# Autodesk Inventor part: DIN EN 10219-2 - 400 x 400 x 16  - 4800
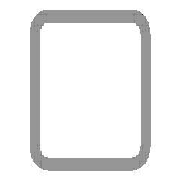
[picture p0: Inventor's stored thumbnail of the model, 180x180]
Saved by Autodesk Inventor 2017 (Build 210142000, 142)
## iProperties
IsCustomPart: 1
Created: 2017-11
Part Number: DIN EN 10219-2 - 400 x 400 x 16  - 4800
Material: Steel, Mild
Description: Cold formed welded structural hollow sections of non-alloy and fine grain structural steel
Document SubType Name: Modeling
Standard: DIN
Designer: iusti
Standard Revision: 2006-07
Standards Organization: DIN
Language: en-US
Size Designation: 400 x 400 x 16
Categories: <MemberInstance><Categories><Category DisplayName="Structural Shapes" InternalName="089c4875-fa83-4c05-b084-43b9cc11f5ed" Mnemonic="GRDR"><CategoryParameter Dis
Stock Number: 400 x 400 x 16
Density: 7.85 g/cm^3
Appearance: Semi-Polished
Mass: 884622 g
Surface Area: 141333 cm^2
Volume: 112691 cm^3
_CCFamilyMember: 142
_CCFamilyDisplayName: DIN EN 10219-2 (Square Hollow Section - Cold Formed) - Cold formed welded structural hollow sections of non-alloy and fine grain structural steel
_FrameMemberDoc: Frame Member File
_Version: 15.0.0
_GetPNFromCC: 1
G_L: 4800.000 mm
G_W: 400.000 mm
G_H: 400.000 mm
+3C696B27-B370-4381-981B-8782BFEB3638+CUTDETAIL1: Cut
Author: iusti
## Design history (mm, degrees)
node "Start plane"
node "End plane"
sketch "Sketch"
  geometry: L1 (-200, -152)-(-200, 152); L2 (-152, 200)-(152, 200); L3 (200, 152)-(200, -152); L4 (152, -200)-(-152, -200); L5 (-152, 184)-(152, 184); L6 (184, 152)-(184, -152); L7 (152, -184)-(-152, -184); L8 (-184, -152)-(-184, 152); L9 (0, 293.918)-(0, -293.918) reference; L10 (-293.918, 0)-(293.918, 0) reference; A1 r 48 centre (-152, -152) between (-200, -152) and (-152, -200); A2 r 48 centre (-152, 152) between (-152, 200) and (-200, 152); A3 r 48 centre (152, 152) between (200, 152) and (152, 200); A4 r 48 centre (152, -152) between (152, -200) and (200, -152); A5 r 32 centre (-152, 152) between (-152, 184) and (-184, 152); A6 r 32 centre (152, 152) between (184, 152) and (152, 184); A7 r 32 centre (152, -152) between (152, -184) and (184, -152); A8 r 32 centre (-152, -152) between (-184, -152) and (-152, -184)
  constraints: 16 end point, 16 point on circle, 8 centre point, 8 tangent, 4 parallel, 3 equal radius, 2 perpendicular, 7 other
  dimensions: "d7" = 48 radius of A1 (= G_IR); "d10" = 400 distance between parallel lines of L2 L4 (= G_H); "d11" = 400 distance between parallel lines of L1 L3 (= G_W); "d12" = 16 distance between parallel lines of L3 L6 (= G_T); "d15" = 200 distance between parallel lines of L2 L10 (= 0.5 x d10); "d16" = 200 distance between parallel lines of L9 L3 (= 0.5 x d11)
extrude "Body" new body sketch "Sketch" stored distance "d3" = 4800 (= G_L); taper "d4" = 0 deg
node "Driven Length"
  sketch "Sketch3"
    geometry: L1 (0, 0)-(10, 0) reference
    constraints: 2 end point, 1 horizontal
  workplane "Work Plane3"
  sketch "Sketch4"
    geometry: L1 (-2, 200)-(12, 200) reference; L2 (-2, 5000)-(12, 5000) reference
    dimensions: "d18" = 4800 distance between parallel lines of L1 L2 (derived)
workplane "Work Plane4"
split "Split1"
body "Solid1"
other parameters: "G_W" = 400 [user parameter; used in 1 equation term], "G_H" = 400 [user parameter; used in 1 equation term], "G_T" = 16 [user parameter; used in 1 equation term], "G_IR" = 48 [user parameter; used in 1 equation term], "G_L" = 4800 (= d18) [user parameter; used in 1 equation term], "G_OFFSET_END" = 0 [user parameter; used in 1 equation term], "d17" = 90 deg
